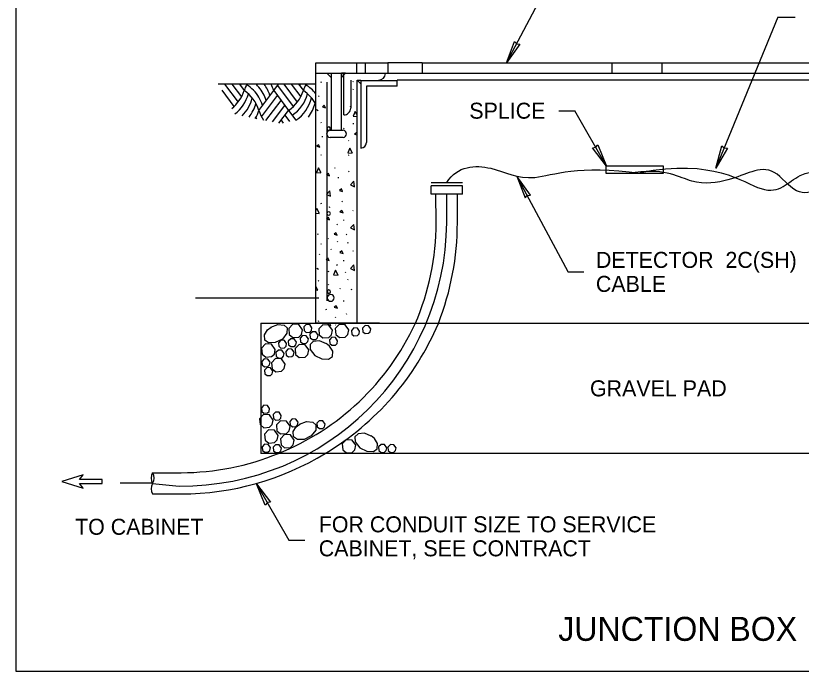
# Model space of a CAD drawing. Extents: x 99862 to 103151, y 100000 to 108076.
# Drawn here: x 99862 to 100648, y 106000 to 106655 of the extents above; entities that cross this region are included whole.
import ezdxf

# ---------------------------------------------------------------- set-up
doc = ezdxf.new("R2010")
doc.units = 0
for name, color, linetype in [('Level 1', 7, 'Continuous'), ('Level 10', 7, 'Continuous'), ('Level 11', 7, 'Continuous'), ('Level 12', 7, 'Continuous'), ('Level 13', 7, 'Continuous'), ('Level 14', 7, 'Continuous'), ('Level 15', 7, 'Continuous'), ('Level 18', 7, 'Continuous'), ('Level 2', 7, 'Continuous'), ('Level 20', 7, 'Continuous'), ('Level 22', 7, 'Continuous'), ('Level 3', 7, 'Continuous'), ('Level 46', 7, 'Continuous'), ('Level 5', 7, 'Continuous'), ('Level 6', 7, 'Continuous'), ('Level 60', 7, 'Continuous'), ('Level 7', 7, 'Continuous'), ('Level 8', 7, 'Continuous')]:
    doc.layers.add(name, color=color, linetype=linetype)

msp = doc.modelspace()

# ---------------------------------------------------------------- linework, layer by layer
at = {"layer": 'Level 1'}
for p, q in [((100162.23, 106347.43), (100162.23, 106597.43)), ((100203.23, 106590.56), (100203.23, 106347.43)), ((100225.98, 106347.43), (100162.23, 106347.43))]:
    msp.add_line(p, q, dxfattribs=at)
msp.add_lwpolyline([(99862, 105999.5), (103151, 105999.5), (103151, 108075.5), (99862, 108075.5)], close=True, dxfattribs=at)
msp.add_lwpolyline([(99862, 105999.5), (103151, 105999.5), (103151, 108075.5), (99862, 108075.5)], close=True, dxfattribs=at)
at = {"layer": 'Level 10'}
for p, q in [((100173.1, 106588.48), (100173.1, 106369.84)), ((100282.54, 106448.09), (100282.36, 106476.57)), ((100303.79, 106448.09), (100303.79, 106476.57)), ((99998.94, 106198.09), (100027.54, 106198.09)), ((99998.67, 106176.84), (100027.54, 106176.84))]:
    msp.add_line(p, q, dxfattribs=at)
for centre, radius, start, end in [((100175.07, 106542.12), 1.72, 90, 270), ((100175.07, 106542.12), 1.72, 270, 90), ((100175.07, 106457.27), 1.72, 90, 270), ((100175.07, 106457.27), 1.72, 270, 90), ((100027.54, 106448.09), 255, 336.66115, 360), ((100027.54, 106448.09), 276.25, 338.615, 0), ((100175.29, 106379.08), 1.72, 90, 270), ((100175.29, 106379.08), 1.72, 270, 90), ((100177.06, 106372.88), 3.44, 90, 270), ((100177.06, 106372.88), 3.44, 270, 90), ((100029.11, 106455.42), 256.56, 291.80939, 335.01983), ((100028.64, 106456.11), 278.26, 300.93532, 336.99524), ((100027.54, 106453.09), 276.25, 270, 301.45227), ((100027.54, 106453.09), 255, 270, 292.45726)]:
    msp.add_arc(centre, radius, start, end, dxfattribs=at)
at = {"layer": 'Level 11'}
msp.add_line((100107.23, 106347.43), (100107.23, 106217.43), dxfattribs=at)
for points in [[(100107.23, 106347.43), (100911.48, 106347.43), (100911.48, 106217.43), (100107.23, 106217.43)], [(100117.15, 106343.45), (100124.06, 106346.19), (100130.42, 106345.64), (100133.44, 106342.77), (100133.34, 106337.61), (100128.76, 106331.75), (100121.67, 106328.21), (100115, 106328.09), (100111.24, 106330.76), (100110.88, 106336.08), (100113.93, 106340.84), (100117.43, 106343.62)], [(100148.79, 106340.86), (100145.09, 106346.12), (100139.19, 106346.46), (100135.08, 106342.2), (100135.67, 106336.24), (100139.32, 106333.21), (100145.15, 106333.63), (100147.89, 106336.29), (100148.78, 106340.86)], [(100158.28, 106343), (100156.06, 106346.15), (100152.52, 106346.36), (100150.05, 106343.8), (100150.41, 106340.23), (100152.6, 106338.41), (100156.1, 106338.66), (100157.74, 106340.25), (100158.28, 106343)], [(100178.8, 106340.46), (100175.1, 106345.73), (100169.2, 106346.06), (100165.09, 106341.81), (100165.68, 106335.84), (100169.33, 106332.81), (100175.16, 106333.23), (100177.9, 106335.89), (100178.79, 106340.46)], [(100195.18, 106340.78), (100191.48, 106346.04), (100185.58, 106346.38), (100181.47, 106342.12), (100182.06, 106336.16), (100185.71, 106333.13), (100191.54, 106333.55), (100194.28, 106336.21), (100195.17, 106340.78)], [(100117.03, 106343.44), (100117.27, 106343.54)], [(100164.48, 106335.71), (100162.26, 106338.87), (100158.72, 106339.07), (100156.26, 106336.52), (100156.62, 106332.94), (100158.8, 106331.12), (100162.3, 106331.37), (100163.95, 106332.97), (100164.48, 106335.71)], [(100206.03, 106339.52), (100203.81, 106342.68), (100200.26, 106342.88), (100197.8, 106340.33), (100198.16, 106336.75), (100200.34, 106334.93), (100203.84, 106335.19), (100205.49, 106336.78), (100206.02, 106339.52)], [(100217.15, 106341.81), (100214.93, 106344.97), (100211.39, 106345.17), (100208.93, 106342.62), (100209.29, 106339.04), (100211.48, 106337.22), (100214.97, 106337.47), (100216.62, 106339.07), (100217.15, 106341.81)], [(100132.93, 106327.24), (100130.71, 106330.4), (100127.17, 106330.6), (100124.7, 106328.05), (100125.06, 106324.47), (100127.25, 106322.65), (100130.75, 106322.9), (100132.39, 106324.5), (100132.92, 106327.24)], [(100142.87, 106328.69), (100140.65, 106331.85), (100137.11, 106332.05), (100134.65, 106329.5), (100135, 106325.92), (100137.19, 106324.1), (100140.69, 106324.35), (100142.33, 106325.95), (100142.86, 106328.69)], [(100154.74, 106331.84), (100152.52, 106335), (100148.98, 106335.2), (100146.52, 106332.65), (100146.87, 106329.07), (100149.06, 106327.25), (100152.56, 106327.5), (100154.2, 106329.1), (100154.74, 106331.84)], [(100183.95, 106330.08), (100181.73, 106333.24), (100178.19, 106333.44), (100175.73, 106330.88), (100176.08, 106327.31), (100178.27, 106325.49), (100181.77, 106325.74), (100183.42, 106327.34), (100183.95, 106330.08)], [(100121.58, 106321.33), (100117.88, 106326.59), (100111.98, 106326.93), (100107.88, 106322.68), (100108.47, 106316.71), (100112.12, 106313.68), (100117.94, 106314.1), (100120.69, 106316.76), (100121.58, 106321.33)], [(100155.08, 106320.8), (100151.38, 106326.06), (100145.48, 106326.4), (100141.38, 106322.14), (100141.97, 106316.18), (100145.62, 106313.14), (100151.45, 106313.57), (100154.19, 106316.23), (100155.08, 106320.8)], [(100172.81, 106327.04), (100165.89, 106329.78), (100159.54, 106329.23), (100156.52, 106326.36), (100156.62, 106321.2), (100161.2, 106315.34), (100168.28, 106311.8), (100174.96, 106311.69), (100178.72, 106314.36), (100179.07, 106319.67), (100176.02, 106324.43), (100172.53, 106327.21)], [(100130.55, 106317.35), (100128.33, 106320.51), (100124.79, 106320.71), (100122.32, 106318.16), (100122.68, 106314.58), (100124.87, 106312.76), (100128.37, 106313.01), (100130.01, 106314.61), (100130.54, 106317.35)], [(100140.44, 106318.46), (100138.22, 106321.62), (100134.68, 106321.82), (100132.21, 106319.27), (100132.57, 106315.69), (100134.76, 106313.87), (100138.26, 106314.12), (100139.9, 106315.72), (100140.44, 106318.46)], [(100116.42, 106308.61), (100114.2, 106311.76), (100110.66, 106311.97), (100108.2, 106309.41), (100108.55, 106305.84), (100110.74, 106304.02), (100114.24, 106304.27), (100115.88, 106305.86), (100116.42, 106308.61)], [(100131.54, 106306.7), (100127.84, 106311.96), (100121.94, 106312.3), (100117.83, 106308.04), (100118.43, 106302.08), (100122.07, 106299.05), (100127.9, 106299.47), (100130.64, 106302.13), (100131.53, 106306.7)], [(100119.17, 106299.76), (100116.95, 106302.91), (100113.41, 106303.12), (100110.95, 106300.56), (100111.3, 106296.99), (100113.49, 106295.17), (100116.99, 106295.42), (100118.64, 106297.02), (100119.17, 106299.76)], [(100115.92, 106262.15), (100113.7, 106265.3), (100110.16, 106265.5), (100107.7, 106262.95), (100108.06, 106259.37), (100110.24, 106257.55), (100113.74, 106257.81), (100115.39, 106259.4), (100115.92, 106262.14)], [(100119.53, 106250.72), (100115.83, 106255.98), (100109.92, 106256.32), (100105.82, 106252.06), (100106.41, 106246.1), (100110.06, 106243.06), (100115.89, 106243.49), (100118.63, 106246.15), (100119.52, 106250.72)], [(100127.61, 106255.33), (100125.39, 106258.48), (100121.85, 106258.69), (100119.39, 106256.13), (100119.75, 106252.56), (100121.93, 106250.74), (100125.43, 106250.99), (100127.08, 106252.58), (100127.61, 106255.33)], [(100144.39, 106248.6), (100142.17, 106251.75), (100138.63, 106251.95), (100136.17, 106249.4), (100136.53, 106245.82), (100138.72, 106244), (100142.21, 106244.26), (100143.86, 106245.85), (100144.39, 106248.6)], [(100136.41, 106244.44), (100132.71, 106249.7), (100126.8, 106250.03), (100122.7, 106245.78), (100123.29, 106239.81), (100126.94, 106236.78), (100132.77, 106237.2), (100135.51, 106239.86), (100136.4, 106244.43)], [(100145.88, 106246.47), (100152.8, 106249.21), (100159.16, 106248.67), (100162.18, 106245.8), (100162.08, 106240.64), (100157.5, 106234.78), (100150.41, 106231.24), (100143.74, 106231.12), (100139.98, 106233.79), (100139.62, 106239.11), (100142.67, 106243.87), (100146.17, 106246.65)], [(100171.43, 106246.69), (100169.21, 106249.84), (100165.66, 106250.05), (100163.2, 106247.49), (100163.56, 106243.92), (100165.74, 106242.1), (100169.25, 106242.35), (100170.89, 106243.95), (100171.42, 106246.69)], [(100124.55, 106235.35), (100120.85, 106240.6), (100114.94, 106240.94), (100110.84, 106236.69), (100111.43, 106230.72), (100115.08, 106227.69), (100120.91, 106228.11), (100123.65, 106230.77), (100124.54, 106235.34)], [(100140.48, 106230.64), (100136.78, 106235.9), (100130.88, 106236.24), (100126.77, 106231.98), (100127.37, 106226.02), (100131.02, 106222.98), (100136.85, 106223.41), (100139.59, 106226.07), (100140.48, 106230.64)], [(100217.66, 106234.74), (100210.75, 106237.49), (100204.39, 106236.94), (100201.37, 106234.07), (100201.47, 106228.91), (100206.05, 106223.05), (100213.14, 106219.51), (100219.81, 106219.39), (100223.57, 106222.06), (100223.93, 106227.38), (100220.88, 106232.14), (100217.38, 106234.92)], [(100202.25, 106225.45), (100198.55, 106230.71), (100192.65, 106231.05), (100188.55, 106226.79), (100189.14, 106220.83), (100192.79, 106217.8), (100198.62, 106218.22), (100201.36, 106220.88), (100202.25, 106225.45)], [(100116.75, 106223.13), (100114.53, 106226.29), (100110.99, 106226.49), (100108.53, 106223.94), (100108.88, 106220.36), (100111.07, 106218.54), (100114.57, 106218.79), (100116.21, 106220.39), (100116.75, 106223.13)], [(100127.74, 106222.72), (100125.52, 106225.87), (100121.98, 106226.07), (100119.51, 106223.52), (100119.87, 106219.94), (100122.06, 106218.12), (100125.56, 106218.38), (100127.2, 106219.97), (100127.74, 106222.71)], [(100233.21, 106223.01), (100230.99, 106226.16), (100227.45, 106226.36), (100224.99, 106223.81), (100225.35, 106220.24), (100227.53, 106218.41), (100231.03, 106218.67), (100232.68, 106220.27), (100233.21, 106223.01)], [(100242.53, 106222.91), (100240.31, 106226.06), (100236.77, 106226.26), (100234.31, 106223.71), (100234.66, 106220.13), (100236.85, 106218.31), (100240.35, 106218.57), (100242, 106220.16), (100242.53, 106222.9)]]:
    msp.add_lwpolyline(points, dxfattribs=at)
at = {"layer": 'Level 12'}
for p, q in [((100293.17, 106448.09), (100293.13, 106476.57)), ((99998.94, 106187.47), (99966.37, 106187.47)), ((99998.94, 106187.22), (100025.51, 106184.72))]:
    msp.add_line(p, q, dxfattribs=at)
msp.add_arc((100027.65, 106450.24), 265.52, 269.53795, 359.53795, dxfattribs=at)
for points in [[(100486.47, 106498.13), (100560.03, 106512.81), (100618.36, 106463.19), (100642.15, 106502.16), (100693.67, 106499.49), (100704.9, 106487.55), (100717.18, 106496.44), (100722.13, 106492.14), (100723.74, 106488.02)], [(100293.36, 106488.12), (100303.44, 106505.23), (100340.88, 106506.61), (100374.54, 106483.95), (100424.16, 106506.61), (100487.09, 106497.45)], [(100701.85, 106487.32), (100688.83, 106485.47), (100676.37, 106483.98), (100666.06, 106481.11), (100642.78, 106473.69), (100620.95, 106504.05), (100598.05, 106499.92), (100577.35, 106490.4), (100537.83, 106483.83), (100513.25, 106502.51), (100481.65, 106498.13)]]:
    msp.add_open_spline(points, degree=3, dxfattribs=at)
at = {"layer": 'Level 13'}
for p, q in [((100070.91, 106586.5), (100084.37, 106568.56)), ((100078.34, 106586.5), (100087.81, 106573.87)), ((100085.76, 106586.5), (100090.49, 106580.2)), ((100120.04, 106580.2), (100124.76, 106586.5)), ((100123.75, 106585.15), (100139.54, 106564.09)), ((100130.17, 106586.5), (100143.62, 106568.56)), ((100137.59, 106586.5), (100147.06, 106573.87)), ((100145.02, 106586.5), (100149.74, 106580.2)), ((100068.03, 106580.44), (100080.29, 106564.09)), ((100105.19, 106560.4), (100120.04, 106580.2)), ((100107.87, 106554.07), (100123.75, 106575.25)), ((100120.04, 106580.2), (100134.89, 106560.4)), ((100112.33, 106550.12), (100127.46, 106570.3)), ((100118.78, 106548.82), (100131.18, 106565.35)), ((100125.23, 106547.52), (100134.89, 106560.4)), ((100134.89, 106560.4), (100142.17, 106550.7)), ((100127.46, 106550.5), (100129.57, 106547.7)), ((100131.18, 106555.45), (100135.87, 106549.2)), ((100277.45, 106488.12), (100308.81, 106488.12)), ((100308.81, 106484.82), (100277.45, 106484.82)), ((100277.45, 106476.57), (100277.45, 106484.82)), ((100308.81, 106476.57), (100308.81, 106484.82)), ((100308.81, 106476.57), (100277.45, 106476.57))]:
    msp.add_line(p, q, dxfattribs=at)
for centre, start, end in [((100122.58, 106573.76), 160.1901, 162.3566), ((100126.29, 106568.81), 151.92534, 162.3566), ((100073.24, 106553.96), 31.33163, 58.48737), ((100076.95, 106558.91), 40.94134, 47.22822), ((100076.81, 106558.91), 17.6434, 40.94141), ((100080.52, 106563.86), 17.6434, 37.03789), ((100084.23, 106568.81), 17.6434, 28.07466), ((100181.84, 106573.76), 160.1901, 162.3566), ((100185.55, 106568.81), 151.92534, 162.3566), ((100132.49, 106553.96), 37.67372, 58.48737), ((100054.68, 106591.59), 308.63268, 342.3566), ((100058.39, 106586.64), 307.33048, 345.01126), ((100069.52, 106549.01), 17.6434, 56.09639), ((100113.93, 106591.59), 303.90361, 342.3566), ((100117.64, 106586.64), 303.90361, 345.01126), ((100128.78, 106549.01), 27.08968, 56.09639), ((100062.1, 106581.69), 314.57512, 346.31988), ((100065.81, 106576.74), 321.86072, 345.77133), ((100073.09, 106553.96), 17.6434, 31.33172), ((100121.35, 106581.69), 303.90361, 346.31988), ((100125.07, 106576.74), 322.16689, 345.77133), ((100069.52, 106571.79), 328.70411, 342.3566), ((100141, 106571.79), 197.64354, 214.34544), ((100137.43, 106566.84), 200.87781, 203.23717)]:
    msp.add_arc(centre, 37.58, start, end, dxfattribs=at)
at = {"layer": 'Level 14'}
for p, q in [((100167.91, 106587.91), (100167.51, 106588.79)), ((100199.7, 106589.17), (100199.3, 106588.58)), ((100165.39, 106574.86), (100165, 106574.27)), ((100199.59, 106581.47), (100199.19, 106580.88)), ((100197.27, 106563.57), (100196.88, 106564.46)), ((100167.91, 106547.48), (100167.51, 106548.36)), ((100190.38, 106542.44), (100189.99, 106541.85)), ((100199.68, 106547.55), (100199.58, 106546.67)), ((100168.52, 106534.6), (100168.42, 106533.72)), ((100195.36, 106530.35), (100194.97, 106529.76)), ((100167.8, 106515.13), (100167.41, 106516.01)), ((100195.06, 106515.74), (100194.67, 106515.15)), ((100181.26, 106502.99), (100180.87, 106502.4)), ((100195.42, 106499.42), (100195.03, 106498.83)), ((100184.54, 106493.6), (100184.44, 106492.72)), ((100167.91, 106466.62), (100167.51, 106467.5)), ((100176.15, 106462.95), (100175.76, 106463.83)), ((100188.76, 106468.87), (100188.36, 106469.75)), ((100199.7, 106460.37), (100199.3, 106459.79)), ((100189.82, 106451), (100189.72, 106450.12)), ((100183.73, 106445.82), (100183.34, 106446.7)), ((100164.59, 106436.08), (100164.2, 106436.96)), ((100174.86, 106432.39), (100174.47, 106431.81)), ((100193.09, 106436.54), (100192.7, 106435.95)), ((100167.91, 106426.19), (100167.51, 106427.07)), ((100184.09, 106428.44), (100183.7, 106429.32)), ((100194.54, 106427.34), (100194.15, 106428.22)), ((100166.1, 106415.87), (100165.71, 106416.75)), ((100178.02, 106420.86), (100177.62, 106421.74)), ((100199.7, 106419.94), (100199.3, 106419.36)), ((100189.82, 106410.57), (100189.72, 106409.69)), ((100183.73, 106405.39), (100183.34, 106406.27)), ((100175.29, 106398.57), (100174.9, 106399.45)), ((100191.99, 106398.53), (100191.6, 106397.94)), ((100165.04, 106389.45), (100164.65, 106390.33)), ((100174.86, 106386.11), (100174.47, 106385.52)), ((100194.33, 106391.12), (100193.94, 106390.53)), ((100186.67, 106382.09), (100186.28, 106381.51)), ((100198.23, 106380.71), (100197.84, 106381.59)), ((100189.82, 106370.14), (100189.72, 106369.27)), ((100172.81, 106360.55), (100172.42, 106361.43)), ((100193.22, 106356.17), (100192.83, 106357.05)), ((100165.15, 106348.98), (100164.76, 106349.86)), ((100181.82, 106353.48), (100181.43, 106352.9)), ((100182.1, 106345.67), (100182.02, 106345.84)), ((100191.12, 106346.43), (100190.73, 106345.84))]:
    msp.add_line(p, q, dxfattribs=at)
for points in [[(100162.81, 106561.14), (100164.48, 106560.36)], [(100171.85, 106562.99), (100170.67, 106565.43), (100168.72, 106563.97), (100171.85, 106562.99)], [(100203.23, 106556.33), (100201.65, 106559.31), (100199.58, 106554.67), (100203.23, 106554.36)], [(100203.23, 106537.41), (100202.97, 106537.96), (100201.02, 106536.49), (100203.23, 106535.8)], [(100166.19, 106523.63), (100165.02, 106526.07), (100163.06, 106524.61), (100166.19, 106523.63)], [(100198.8, 106517.65), (100196.16, 106522.63), (100194.11, 106518.04), (100198.7, 106517.65)], [(100167.46, 106497.83), (100164.82, 106502.81), (100162.77, 106498.22), (100167.36, 106497.83)], [(100175.87, 106494.77), (100174.7, 106497.22), (100172.75, 106495.75), (100175.87, 106494.77)], [(100201, 106483.9), (100200.22, 106489.48), (100196.73, 106485.87), (100200.91, 106483.93)], [(100177.01, 106474.43), (100176.24, 106480.01), (100172.74, 106476.4), (100176.92, 106474.46)], [(100188.89, 106479.31), (100187.72, 106481.75), (100185.77, 106480.29), (100188.89, 106479.31)], [(100165.74, 106457.26), (100163.1, 106462.24), (100162.23, 106460.3)], [(100162.23, 106457.55), (100165.64, 106457.26)], [(100189.44, 106457.83), (100188.27, 106460.27), (100186.31, 106458.81), (100189.44, 106457.83)], [(100175.91, 106450.85), (100174.74, 106453.29), (100172.79, 106451.83), (100175.91, 106450.85)], [(100201, 106440.8), (100200.22, 106446.38), (100196.73, 106442.77), (100200.91, 106440.83)], [(100183.53, 106435.56), (100182.36, 106438), (100180.41, 106436.54), (100183.53, 106435.56)], [(100189.44, 106417.4), (100188.27, 106419.85), (100186.31, 106418.38), (100189.44, 106417.4)], [(100175.53, 106410.42), (100174.36, 106412.86), (100172.4, 106411.4), (100175.53, 106410.42)], [(100163.26, 106402.49), (100164.94, 106401.71)], [(100201, 106400.37), (100200.22, 106405.96), (100196.73, 106402.34), (100200.91, 106400.41)], [(100184.64, 106395.64), (100182.01, 106400.62), (100179.95, 106396.03), (100184.55, 106395.64)], [(100164.21, 106380.62), (100162.23, 106384.34)], [(100162.23, 106380.78), (100164.11, 106380.62)], [(100183.7, 106362.51), (100182.53, 106364.95), (100180.57, 106363.49), (100183.7, 106362.51)], [(100177.14, 106345.3), (100175.97, 106347.75), (100174.01, 106346.28), (100177.14, 106345.3)]]:
    msp.add_lwpolyline(points, dxfattribs=at)
at = {"layer": 'Level 15'}
for p, q in [((100352.95, 106607.83), (100397.49, 106691.83)), ((100624.44, 106653.71), (100641.67, 106653.71)), ((100405.1, 106560.04), (100421.1, 106560.04)), ((100453.06, 106504.68), (100421.1, 106560.04)), ((100414.54, 106399.03), (100363.37, 106494.42)), ((100414.34, 106398.87), (100430.34, 106398.87)), ((100165.06, 106372.73), (100041.69, 106372.73)), ((100102.85, 106187.01), (100135.35, 106130.71)), ((100135.35, 106130.71), (100151.35, 106130.71))]:
    msp.add_line(p, q, dxfattribs=at)
msp.add_lwpolyline([(100624.44, 106653.71), (100562.37, 106502.65)], dxfattribs=at)
for points in [[(100352.95, 106607.83), (100361.01, 106629.39), (100363.15, 106627.06), (100366.29, 106626.6)], [(100453.06, 106504.68), (100439.06, 106522.96), (100442.18, 106523.53), (100444.23, 106525.94)], [(100562.37, 106502.65), (100568.29, 106524.9), (100570.65, 106522.79), (100573.81, 106522.64)], [(100363.37, 106494.42), (100371.53, 106472.89), (100373.66, 106475.23), (100376.79, 106475.71)], [(100102.85, 106187.01), (100116.85, 106168.73), (100113.73, 106168.15), (100111.68, 106165.74)]]:
    msp.add_lwpolyline(points, close=True, dxfattribs=at)
for centre, start, end in [((100008.36, 106192.66), 150, 210), ((99989.52, 106192.66), 330, 30), ((100008.36, 106181.78), 150, 206.99342)]:
    msp.add_arc(centre, 10.88, start, end, dxfattribs=at)
at = {"layer": 'Level 2'}
for p, q in [((100190.1, 106555.83), (100190.1, 106597.36)), ((100263.9, 106597.41), (100815.48, 106597.41)), ((100197.05, 106590.56), (100197.05, 106562.63)), ((100519.5, 106590.63), (100243.46, 106590.63)), ((100688.05, 106590.63), (100519.5, 106590.63))]:
    msp.add_line(p, q, dxfattribs=at)
for centre, start, end in [((100224.97, 106597.36), 270, 360), ((100190.24, 106562.63), 268.83452, 0)]:
    msp.add_arc(centre, 6.81, start, end, dxfattribs=at)
at = {"layer": 'Level 22'}
for p, q in [((100162.23, 106586.5), (100064.67, 106586.5)), ((100162.23, 106586.5), (100109.59, 106586.5)), ((100119.73, 106347.43), (100162.23, 106347.43))]:
    msp.add_line(p, q, dxfattribs=at)
at = {"layer": 'Level 3'}
for p, q in [((100162.23, 106607.75), (100203.23, 106607.75)), ((100162.23, 106597.34), (100162.23, 106607.75)), ((100203.23, 106607.83), (100234.14, 106607.85)), ((100203.23, 106597.43), (100203.23, 106607.83)), ((100211.89, 106597.43), (100211.89, 106607.83)), ((100234.14, 106607.85), (100234.14, 106597.43)), ((100268.46, 106607.85), (100234.14, 106607.85)), ((100268.46, 106607.85), (100268.46, 106597.45)), ((100268.46, 106607.75), (100809.5, 106607.75)), ((100458.46, 106597.42), (100458.46, 106607.75)), ((100458.46, 106607.75), (100508.34, 106607.75)), ((100508.34, 106607.75), (100508.34, 106597.42)), ((100162.23, 106597.43), (100263.9, 106597.43))]:
    msp.add_line(p, q, dxfattribs=at)
at = {"layer": 'Level 46'}
msp.add_lwpolyline([(99948.44, 106187.2), (99948.46, 106191.16), (99925.96, 106191.24), (99929.51, 106195.94), (99908.17, 106189.32), (99929.46, 106182.61), (99925.95, 106187.28), (99948.44, 106187.2)], dxfattribs=at)
at = {"layer": 'Level 5'}
msp.add_lwpolyline([(100452.53, 106504.83), (100509.67, 106504.83), (100509.67, 106497.13), (100452.53, 106497.13)], close=True, dxfattribs=at)
at = {"layer": 'Level 6'}
for p, q in [((100207.13, 106590.33), (100207.13, 106522.72)), ((100207.13, 106590.33), (100243.46, 106590.33)), ((100243.46, 106584.69), (100243.46, 106590.33)), ((100212.77, 106584.69), (100212.77, 106528.13)), ((100243.46, 106584.69), (100212.77, 106584.69))]:
    msp.add_line(p, q, dxfattribs=at)
msp.add_arc((100207.36, 106528.13), 5.41, 270, 0, dxfattribs=at)
at = {"layer": 'Level 60'}
msp.add_line((99862, 105999.5), (99862, 105999.5), dxfattribs=at)
msp.add_line((99862, 105999.5), (99862, 105999.5), dxfattribs=at)
msp.add_line((99862, 105999.5), (99862, 105999.5), dxfattribs=at)
msp.add_line((99862, 105999.5), (99862, 105999.5), dxfattribs=at)
at = {"layer": 'Level 7'}
for p, q in [((100177.42, 106597.43), (100177.42, 106540.42)), ((100187.73, 106540.42), (100187.73, 106597.43)), ((100176.37, 106540.42), (100189.45, 106540.42)), ((100191.45, 106536.92), (100191.45, 106536.89)), ((100189.45, 106533.39), (100176.37, 106533.39))]:
    msp.add_line(p, q, dxfattribs=at)
for centre, start, end in [((100176.37, 106536.92), 90, 180), ((100176.37, 106536.89), 180, 270), ((100189.45, 106536.92), 0, 90), ((100189.45, 106536.89), 270, 0)]:
    msp.add_arc(centre, 3.5, start, end, dxfattribs=at)
at = {"layer": 'Level 8'}
for points in [[(100173.3, 106597.43), (100177.42, 106597.43), (100177.42, 106597.37), (100177.41, 106593.39), (100177.41, 106593.21)], [(100191.85, 106597.5), (100187.73, 106597.5), (100187.73, 106597.43), (100187.73, 106593.45), (100187.73, 106593.27)]]:
    msp.add_lwpolyline(points, close=True, dxfattribs=at)
msp.add_lwpolyline([(100207.13, 106587), (100203.65, 106590.55), (100207.13, 106590.55), (100207.13, 106587)], dxfattribs=at)

# ---------------------------------------------------------------- texts
at = {"layer": 'Level 18'}
msp.add_text(' SPLICE', height=16, dxfattribs=at).set_placement((100309.78, 106552.04))
at = {"layer": 'Level 20'}
for s, height, p in [('DETECTOR  2C(SH) ', 16, (100442.34, 106402.87)), ('CABLE', 16, (100442.34, 106378.87)), ('TO CABINET', 16, (99921.38, 106135.99)), ('JUNCTION BOX ', 24, (100404.71, 106029.93))]:
    msp.add_text(s, height=height, dxfattribs=at).set_placement(p)
for s, p in [('GRAVEL PAD', (100436.42, 106274.43)), ('FOR CONDUIT SIZE TO SERVICE ', (100165.12, 106138.46)), ('CABINET, SEE CONTRACT', (100165.12, 106114.46))]:
    msp.add_text(s, height=16, rotation=360, dxfattribs=at).set_placement(p)

doc.saveas('drawing.dxf')
